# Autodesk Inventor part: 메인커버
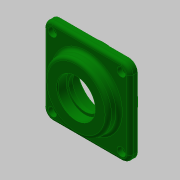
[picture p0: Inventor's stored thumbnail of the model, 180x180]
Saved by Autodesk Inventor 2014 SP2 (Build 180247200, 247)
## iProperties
Created: 2018-09
Part Number: 메인커버
Material: 알루미늄 6061
Document SubType Name: Modeling
Designer: mduedu
Density: 1 g/cm^3
Appearance: 진녹색
Author: mduedu
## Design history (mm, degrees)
sketch "스케치1"
  geometry: L1 (-40, -40)-(40, -40); L2 (40, -40)-(40, 40); L3 (40, 40)-(-40, 40); L4 (-40, 40)-(-40, -40); L5 (-40, -40)-(40, 40); L6 (40, -40)-(-40, 40); 1 further point
  constraints: 12 end point, 2 midpoint, 2 parallel, 1 horizontal, 1 perpendicular
  dimensions: "d0" = 80 distance of L3.end L2.end; "d1" = 80 distance of L2.end L1.end
extrude "돌출1" new body sketch "스케치1" distance "d2" = 7; taper "d3" = 0 deg
sketch "스케치2"
  geometry: C1 r 30 at (0, 0); 1 further point
  constraints: 1 centre point, 1 coincident
  dimensions: "d4" = 60 diameter of C1
extrude "돌출2" join sketch "스케치2" distance "d5" = 10; taper "d6" = 0 deg
sketch "스케치3"
  geometry: C1 r 32.5 at (0, 0); 1 further point
  constraints: 1 centre point, 1 coincident
  dimensions: "d7" = 65 diameter of C1
extrude "돌출3" join sketch "스케치3" distance "d8" = 9; taper "d9" = 0 deg
sketch "스케치4"
  geometry: L1 (-32.5, -9)-(32.5, -9) reference; L2 (30, 17)-(-30, 17) reference; L3 (0, 17)-(0, -9); L4 (0, -9)-(23.5, -9); L5 (23.5, -9)-(23.5, 5); L6 (23.5, 5)-(0, 5); L7 (0, 5)-(0, -9); L8 (0, 5)-(15, 5); L9 (15, 5)-(15, 8.7); L10 (15, 8.7)-(0, 8.7); L11 (0, 8.7)-(0, 5); L12 (0, 8.7)-(17.5, 8.7); L13 (17.5, 8.7)-(17.5, 17); L14 (17.5, 17)-(0, 17); L15 (0, 17)-(0, 8.7); 1 further point
  constraints: 26 end point, 6 parallel, 3 horizontal, 3 perpendicular, 2 midpoint, 1 point on line
  dimensions: "d10" = 14 distance of L4.end L5.end; "d12" = 8.3 distance of L12.end L13.end; "d13" = 35 diameter of L13 L3; "d14" = 30 diameter of L9 L3; "d15" = 47 diameter of L5 L3
revolve "회전1" sketch "스케치4" stored, may be unused: angle "d16" = 90 deg
fillet "모깎기1" dims "d17" = 8
fillet "모깎기2" dims "d18" = 3
fillet "모깎기3" dims "d19" = 3
chamfer "모따기1" distance "d20" = 0.8; stored, may be unused: second distance "d21" = 2, angle "d22" = 30 deg
chamfer "모따기2" distance "d23" = 1; stored, may be unused: second distance "d24" = 2, angle "d25" = 30 deg
fillet "모깎기4" dims "d26" = 0.3
sketch "스케치5"
  geometry: A1 r 8 centre (-32, 32) between (-32, 40) and (-40, 32) reference; A2 r 8 centre (-32, -32) between (-40, -32) and (-32, -40) reference; A3 r 8 centre (32, -32) between (32, -40) and (40, -32) reference; A4 r 8 centre (32, 32) between (40, 32) and (32, 40) reference; 5 further points
  constraints: 4 coincident
hole "구멍1" sketch "스케치5" at (-32, 32), (32, 32), (32, -32), (-32, -32) diameter "d27" = 4.5; stored, may be unused: countersink angle "d31" = 90 deg, drill point angle "d33" = 118 deg; dims "d28" = 6, "d29" = 8, "d30" = 4.4, "d32" = 8
node "솔리드1"
